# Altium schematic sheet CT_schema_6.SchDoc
size 255 x 245 mm
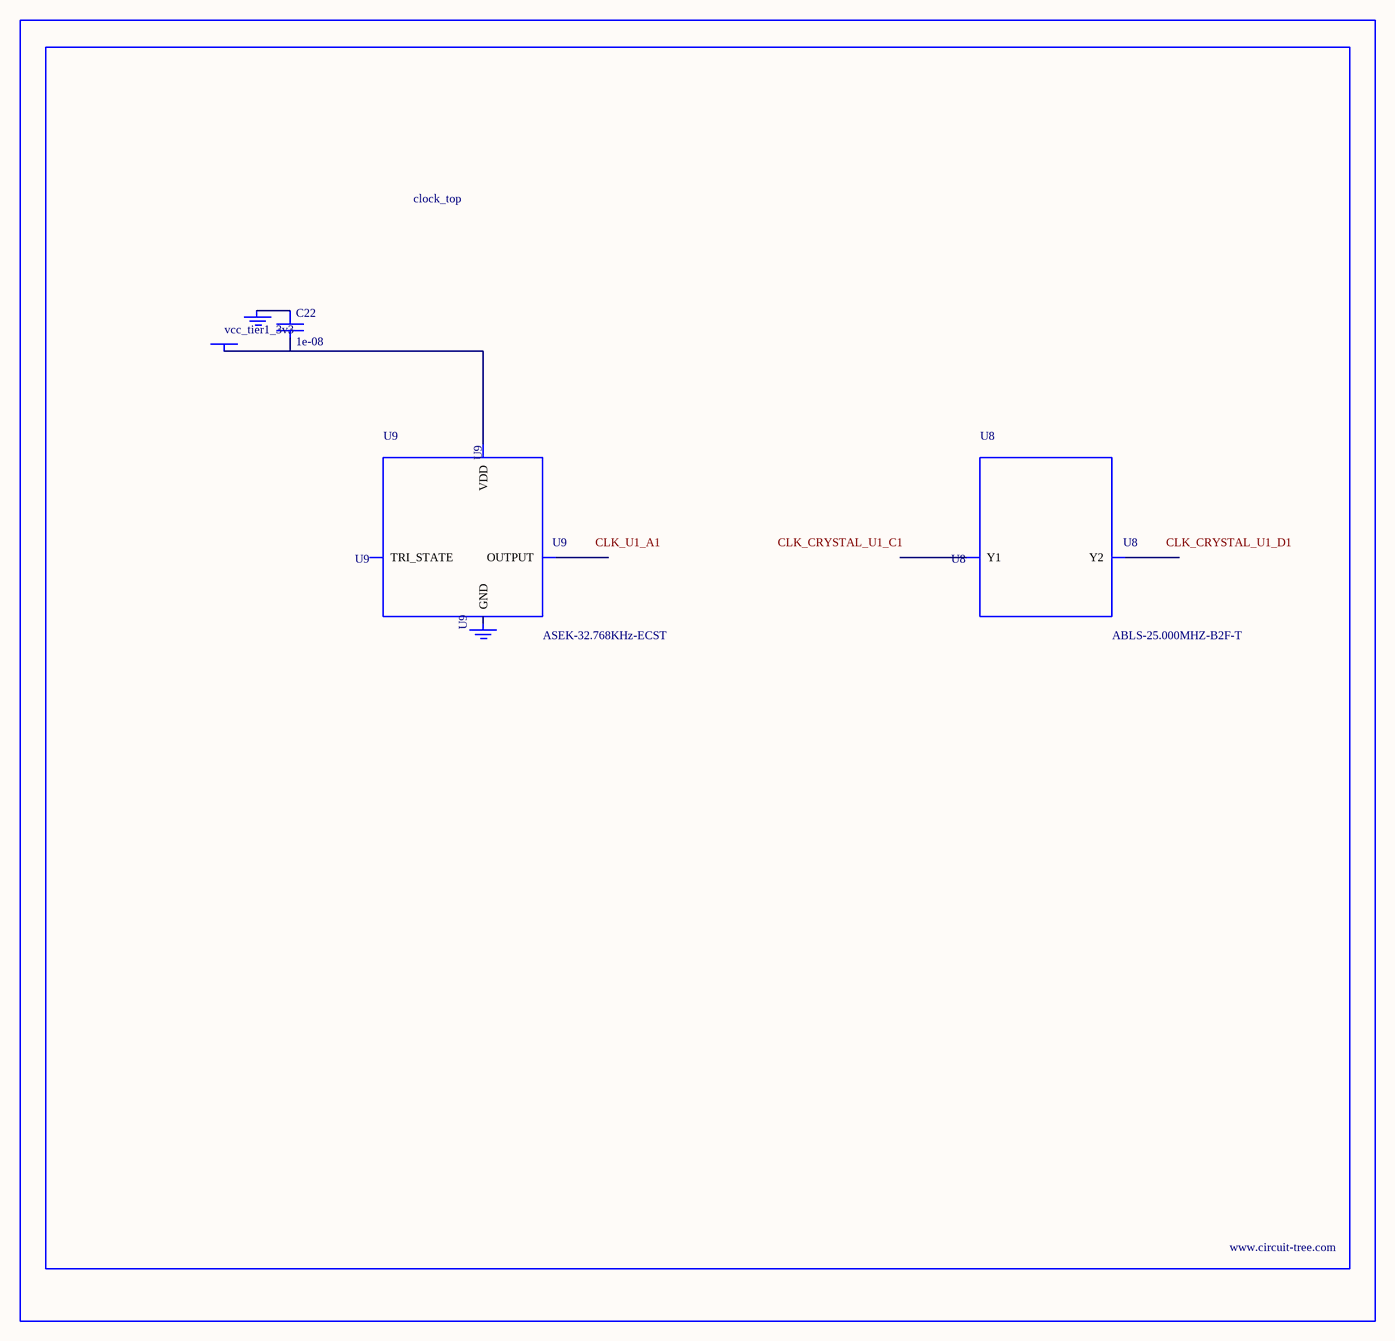
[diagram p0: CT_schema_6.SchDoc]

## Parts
BORDER5  (no value)
C22  1e-08  [C0402]
GND_INSTANCE_5_0  (no value)
GND_INSTANCE_5_1  (no value)
POWER_INSTANCE_5_0  vcc_tier1_3v3
U8  ABLS-25.000MHZ-B2F-T  [ABLS-25.000MHZ-B2F-T]
U9  ASEK-32.768KHz-ECST  [ASEK]

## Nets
NetC22_1: C22.1 GND_INSTANCE_5_0.0(GND)
NetC22_2: C22.2 POWER_INSTANCE_5_0.0(PWR) U9.4(VDD)

Not connected (* = marked no-connect by the designer): GND_INSTANCE_5_1 0(GND); U8 1(Y1) 2(Y2); U9 1(TRI_STATE) 2(GND) 3(OUTPUT)

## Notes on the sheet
- Labels drawn without touching a wire or pin: CLK_CRYSTAL_U1_C1, CLK_CRYSTAL_U1_D1, CLK_U1_A1

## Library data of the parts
BORDER5 = BORDER_PAGE5
C22 = C0402C103K3RAC
GND_INSTANCE_5_0 GND_INSTANCE_5_1 = GND
POWER_INSTANCE_5_0 = PWR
